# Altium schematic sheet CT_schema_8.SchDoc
size 147 x 119 mm
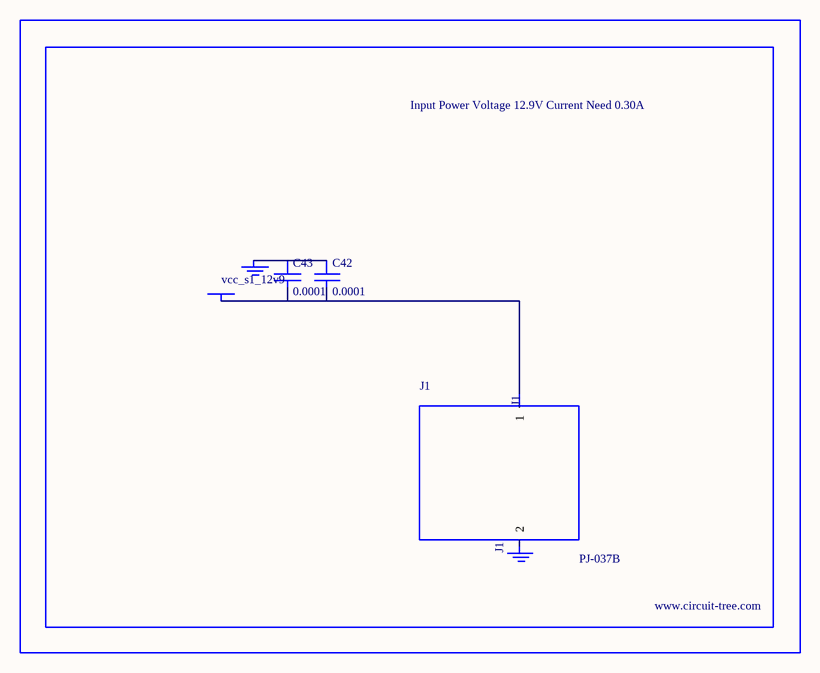
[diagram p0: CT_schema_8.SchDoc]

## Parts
BORDER7  (no value)
C42  0.0001  [EXV-9H]
C43  0.0001  [EXV-9H]
GND_INSTANCE_7_0  (no value)
GND_INSTANCE_7_1  (no value)
J1  PJ-037B  [PJ-037B_PACKAGE]
POWER_INSTANCE_7_0  vcc_s1_12v9

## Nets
NetC42_1: C42.1 C43.1 GND_INSTANCE_7_0.0(GND)
NetC42_2: C42.2 C43.2 J1.1 POWER_INSTANCE_7_0.0(PWR)

Not connected (* = marked no-connect by the designer): GND_INSTANCE_7_1 0(GND); J1 2

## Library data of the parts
BORDER7 = BORDER_PAGE7
C42 C43 = EDK107M035A9HAA
GND_INSTANCE_7_0 GND_INSTANCE_7_1 = GND
POWER_INSTANCE_7_0 = PWR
